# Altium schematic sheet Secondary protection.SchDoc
size 431 x 279 mm; Date: Not shown in title block; ApprovedBy: Not shown in title block; CheckedBy: Not shown in title block; Author: Not shown in title block; CompanyName: Not shown in title block; Engineer: Not shown in title block; Organization: Not shown in title block; Address1: Not shown in title block; Address2: Not shown in title block; Address3: Not shown in title block; Address4: Not shown in title block; DocumentNumber: 1; Revision: Use project parameter SCH_Rev; SheetNumber: 2; SheetTotal: 3; PageSetup: Record=PageOptions¦CenterHorizontal=True¦CenterVertical=True¦PrintScale=1.00¦XCorrection=1.00¦YCorrection=1.00¦PrintKind=0¦BorderSize=5000000¦LeftOffset=0¦BottomOffset=0¦Orientation=2¦PaperLength=1000¦PaperWidth=1000¦Scale=100¦PaperSource=15¦PrintQuality=600¦MediaType=1¦DitherType=10¦PaperKind=Letter¦PrintScaleMode=1
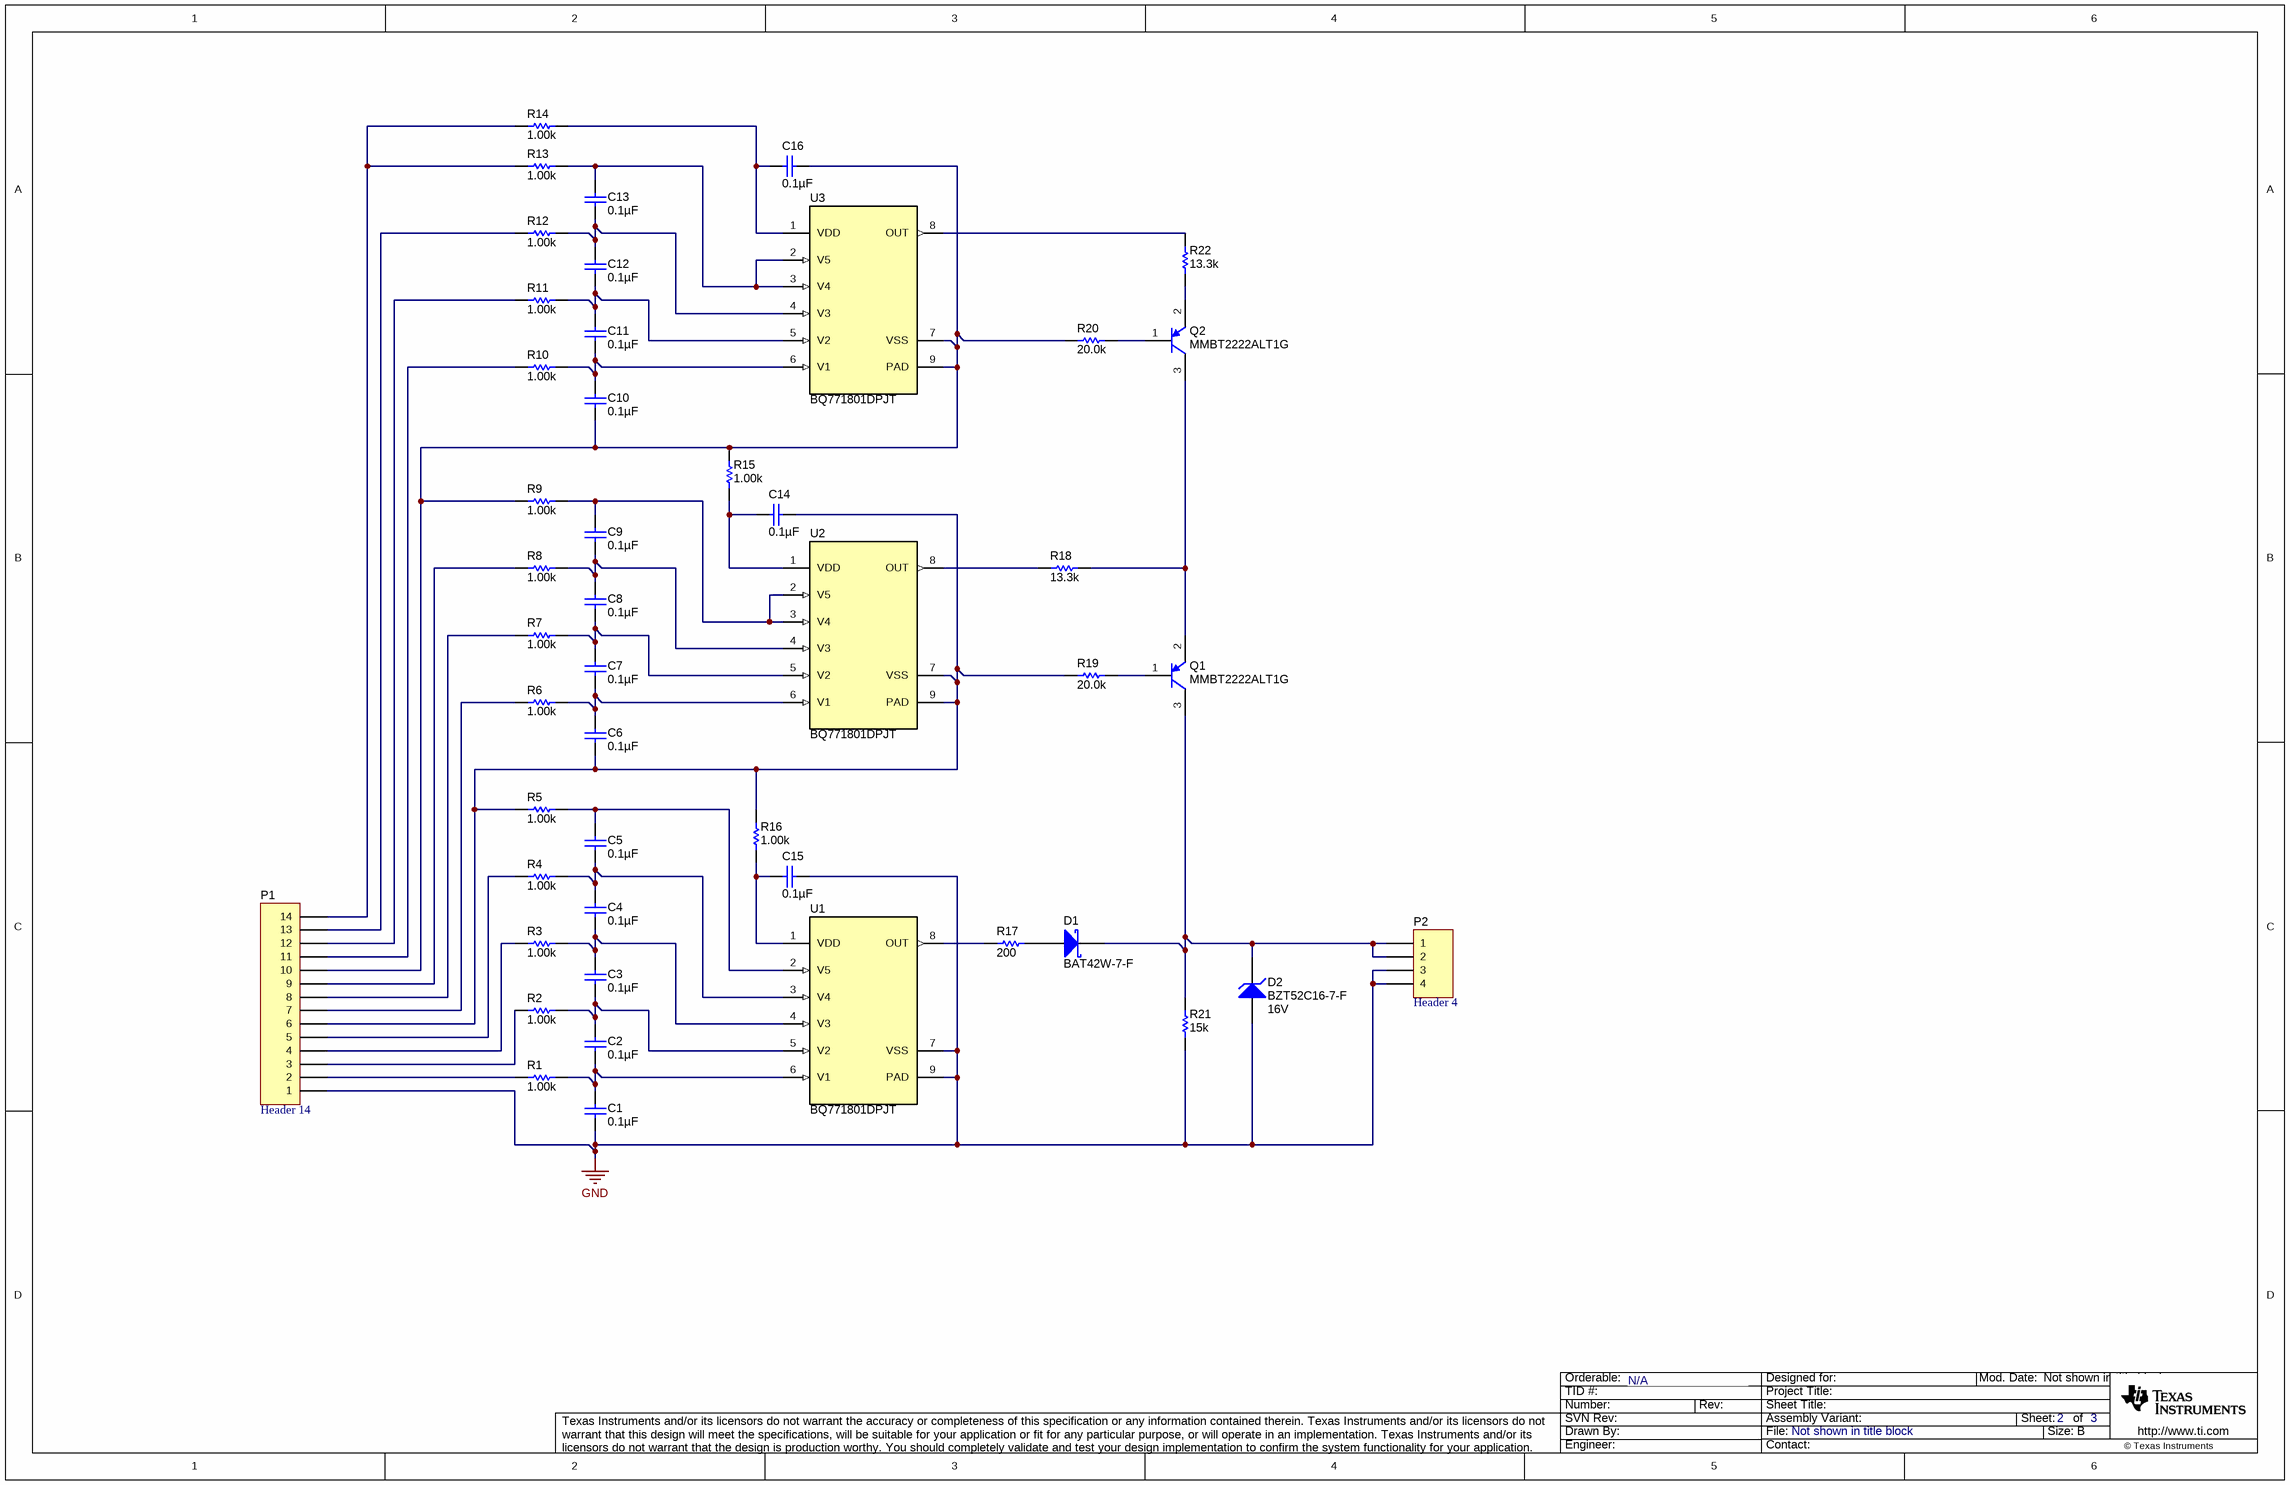
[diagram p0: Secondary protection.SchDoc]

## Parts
C1  ValueDisplayed: 0.1µF  [0603]  (hidden comment: GRM188R71H104KA93D)
C2  ValueDisplayed: 0.1µF  [0603]  (hidden comment: GRM188R71H104KA93D)
C3  ValueDisplayed: 0.1µF  [0603]  (hidden comment: GRM188R71H104KA93D)
C4  ValueDisplayed: 0.1µF  [0603]  (hidden comment: GRM188R71H104KA93D)
C5  ValueDisplayed: 0.1µF  [0603]  (hidden comment: GRM188R71H104KA93D)
C6  ValueDisplayed: 0.1µF  [0603]  (hidden comment: GRM188R71H104KA93D)
C7  ValueDisplayed: 0.1µF  [0603]  (hidden comment: GRM188R71H104KA93D)
C8  ValueDisplayed: 0.1µF  [0603]  (hidden comment: GRM188R71H104KA93D)
C9  ValueDisplayed: 0.1µF  [0603]  (hidden comment: GRM188R71H104KA93D)
C10  ValueDisplayed: 0.1µF  [0603]  (hidden comment: GRM188R71H104KA93D)
C11  ValueDisplayed: 0.1µF  [0603]  (hidden comment: GRM188R71H104KA93D)
C12  ValueDisplayed: 0.1µF  [0603]  (hidden comment: GRM188R71H104KA93D)
C13  ValueDisplayed: 0.1µF  [0603]  (hidden comment: GRM188R71H104KA93D)
C14  ValueDisplayed: 0.1µF  [0603]  (hidden comment: GRM188R71H104KA93D)
C15  ValueDisplayed: 0.1µF  [0603]  (hidden comment: GRM188R71H104KA93D)
C16  ValueDisplayed: 0.1µF  [0603]  (hidden comment: GRM188R71H104KA93D)
D1  BAT42W-7-F  [SOD-123]
D2  BZT52C16-7-F  value 16V  [SOD-123]
P1  Header 14  [HDR1X14]
P2  Header 4  [HDR1X4]
Q1  MMBT2222ALT1G  [SOT-23]
Q2  MMBT2222ALT1G  [SOT-23]
R1  ValueDisplayed: 1.00k  [0603]  (hidden comment: CRCW06031K00FKEA)
R2  ValueDisplayed: 1.00k  [0603]  (hidden comment: CRCW06031K00FKEA)
R3  ValueDisplayed: 1.00k  [0603]  (hidden comment: CRCW06031K00FKEA)
R4  ValueDisplayed: 1.00k  [0603]  (hidden comment: CRCW06031K00FKEA)
R5  ValueDisplayed: 1.00k  [0603]  (hidden comment: CRCW06031K00FKEA)
R6  ValueDisplayed: 1.00k  [0603]  (hidden comment: CRCW06031K00FKEA)
R7  ValueDisplayed: 1.00k  [0603]  (hidden comment: CRCW06031K00FKEA)
R8  ValueDisplayed: 1.00k  [0603]  (hidden comment: CRCW06031K00FKEA)
R9  ValueDisplayed: 1.00k  [0603]  (hidden comment: CRCW06031K00FKEA)
R10  ValueDisplayed: 1.00k  [0603]  (hidden comment: CRCW06031K00FKEA)
R11  ValueDisplayed: 1.00k  [0603]  (hidden comment: CRCW06031K00FKEA)
R12  ValueDisplayed: 1.00k  [0603]  (hidden comment: CRCW06031K00FKEA)
R13  ValueDisplayed: 1.00k  [0603]  (hidden comment: CRCW06031K00FKEA)
R14  ValueDisplayed: 1.00k  [0603]  (hidden comment: CRCW06031K00FKEA)
R15  ValueDisplayed: 1.00k  [0603]  (hidden comment: CRCW06031K00FKEA)
R16  ValueDisplayed: 1.00k  [0603]  (hidden comment: CRCW06031K00FKEA)
R17  ValueDisplayed: 200  [0603]  (hidden comment: CRCW0603200RJNEA)
R18  ValueDisplayed: 13.3k  [0603]  (hidden comment: CRCW060313K3FKEA)
R19  ValueDisplayed: 20.0k  [0603]  (hidden comment: CRCW060320K0FKEA)
R20  ValueDisplayed: 20.0k  [0603]  (hidden comment: CRCW060320K0FKEA)
R21  ValueDisplayed: 15k  [0603]  (hidden comment: CRCW060315K0JNEA)
R22  ValueDisplayed: 13.3k  [0603]  (hidden comment: CRCW060313K3FKEA)
U1  BQ771801DPJT  [DPJ0008A]
U2  BQ771801DPJT  [DPJ0008A]
U3  BQ771801DPJT  [DPJ0008A]

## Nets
GND: C1.2 C15.2 D2.2(A) P1.1 P2.3 P2.4 R21.2 U1.7(VSS) U1.9(PAD)
NetC1_1: C1.1 C2.2 R1.1 U1.6(V1)
NetC2_1: C2.1 C3.2 R2.1 U1.5(V2)
NetC3_1: C3.1 C4.2 R3.1 U1.4(V3)
NetC4_1: C4.1 C5.2 R4.1 U1.3(V4)
NetC5_1: C5.1 R5.1 U1.2(V5)
NetC6_1: C6.1 C7.2 R6.1 U2.6(V1)
NetC6_2: C6.2 C14.2 P1.6 R5.2 R16.1 R19.1 U2.7(VSS) U2.9(PAD)
NetC7_1: C7.1 C8.2 R7.1 U2.5(V2)
NetC8_1: C8.1 C9.2 R8.1 U2.4(V3)
NetC9_1: C9.1 R9.1 U2.2(V5) U2.3(V4)
NetC10_1: C10.1 C11.2 R10.1 U3.6(V1)
NetC10_2: C10.2 C16.2 P1.10 R9.2 R15.1 R20.1 U3.7(VSS) U3.9(PAD)
NetC11_1: C11.1 C12.2 R11.1 U3.5(V2)
NetC12_1: C12.1 C13.2 R12.1 U3.4(V3)
NetC13_1: C13.1 R13.1 U3.2(V5) U3.3(V4)
NetC14_1: C14.1 R15.2 U2.1(VDD)
NetC15_1: C15.1 R16.2 U1.1(VDD)
NetC16_1: C16.1 R14.1 U3.1(VDD)
NetD1_1: D1.1(K) D2.1(K) P2.1 P2.2 Q1.3(C) R21.1
NetD1_2: D1.2(A) R17.2
NetP1_2: P1.2 R1.2
NetP1_3: P1.3 R2.2
NetP1_4: P1.4 R3.2
NetP1_5: P1.5 R4.2
NetP1_7: P1.7 R6.2
NetP1_8: P1.8 R7.2
NetP1_9: P1.9 R8.2
NetP1_11: P1.11 R10.2
NetP1_12: P1.12 R11.2
NetP1_13: P1.13 R12.2
NetP1_14: P1.14 R13.2 R14.2
NetQ1_1: Q1.1(B) R19.2
NetQ1_2: Q1.2(E) Q2.3(C) R18.2
NetQ2_1: Q2.1(B) R20.2
NetQ2_2: Q2.2(E) R22.2
NetR17_1: R17.1 U1.8(OUT)
NetR18_1: R18.1 U2.8(OUT)
NetR22_1: R22.1 U3.8(OUT)

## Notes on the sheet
- N/A

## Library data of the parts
C1-C16 = GRM188R71H104KA93D: CAP, CERM, 0.1 µF, 50 V,+/- 10%, X7R, 0603; Manufacturer: MuRata; Polarized: N; CompType: Capacitor; Value: 0.1uF; U/M: EA; Cap_F: 0.0000001; Tolerance_%: 10; VDC_V: 50; Value2: 50V; TaMin_C: -55; TaMax_C: 125; SizeArea_mm2: 1.28; SizeAreaWB_mm2: 4.68; SizeX_mm: 1.6; SizeY_mm: 0.8; SizeZ_mm: 1; AEC Category: Q200; Green_Lifecycle: Active; Green_REACh: Passed
D1 = BAT42W-7-F: Diode, Schottky, 30 V, 0.2 A, SOD-123; Manufacturer: Diodes Inc.; U/M: EA; Vf_V: 1; Value: 30V; Value1: 0.2A; Value2: 1V; Io_A: 0.2; Vr_V: 30; SizeAreaWB_mm2: 13.095; SizeArea_mm2: 6.545; SizeX_mm: 3.85; SizeY_mm: 1.7; SizeZ_mm: 1.35; AEC Category: Q101; Green_Lifecycle: Not Set; Green_REACh: Incomplete
D2 = BZT52C16-7-F: Diode, Zener, 16 V, 500 mW, AEC-Q101, SOD-123; Manufacturer: Diodes Inc.; SymbolCreator: a0412235; U/M: EA; Power_W: 0.5; Vz_V: 16; Value1: 0.5W; RJA_CperW: 338; SizeAreaWB_mm2: 13.095; SizeArea_mm2: 6.545; SizeX_mm: 3.85; SizeY_mm: 1.7; SizeZ_mm: 1.35; AEC Category: Q101; AEC Qualified: Y
P1 = Header 14: Header, 14-Pin
P2 = Header 4: Header, 4-Pin
Q1 Q2 = MMBT3906-7-F, Diodes Inc.: Transistor, PNP, 40 V, 0.6 A, SOT-23; CompType: BJT; PNP: 1; NPN: 0; Vceo_V: 40; Vcesat1_V: 0.25; Value: 40 V; IcRated_A: 0.2; Value1: 0.2 A; HfeMax: 400; TaMin_C: -55; TaMax_C: 150; SizeAreaWB_mm2: 14; SizeArea_mm2: 7.5; SizeX_mm: 2.5; SizeY_mm: 3; SizeZ_mm: 1.1; U/M: EA; AEC Category: Q101; Green_Lifecycle: Active; Green_REACh: Passed
R1-R16 = CRCW06031K00FKEA: RES, 1.00 k, 1%, 0.1 W, 0603; Manufacturer: Vishay-Dale; CompType: Resistor; Value: 1.00k; Res_ohm: 1000; Value_Code: 1k00; Tolerance_%: 1; Power_W: 0.1; Value2: 0.1W; VDC_V: 75; TempCo: 100 ppm/C; SizeArea_mm2: 1.28; SizeX_mm: 1.6; SizeY_mm: 0.8; EIA_Code: E96; U/M: EA; AEC Category: Q200; Green_Lifecycle: Active; Green_REACh: Passed
R17 = CRCW0603200RJNEA: RES, 200, 5%, 0.1 W, 0603; Manufacturer: Vishay-Dale; CompType: Resistor; Value: 200; Value_Code: 200R; Tolerance_%: 5; Power_W: 0.1; Value2: 0.1W; VDC_V: 75; TempCo: 200 ppm/C; SizeArea_mm2: 1.28; SizeX_mm: 1.6; SizeY_mm: 0.8; SizeZ_mm: 1; EIA_Code: E24; U/M: EA; AEC Category: Q200; Green_Lifecycle: Active; Green_REACh: Passed
R18 R22 = CRCW060313K3FKEA: RES, 13.3 k, 1%, 0.1 W, 0603; Manufacturer: Vishay-Dale; CompType: Resistor; Value: 13.3k; Res_ohm: 13300; Value_Code: 13k3; Tolerance_%: 1; Power_W: 0.1; Value2: 0.1W; VDC_V: 75; TempCo: 100 ppm/C; SizeArea_mm2: 1.28; SizeX_mm: 1.6; SizeY_mm: 0.8; EIA_Code: E96; U/M: EA; AEC Category: Q200; Green_Lifecycle: Active; Green_REACh: Passed
R19 R20 = CRCW060320K0FKEA: RES, 20.0 k, 1%, 0.1 W, 0603; Manufacturer: Vishay-Dale; CompType: Resistor; Value: 20.0k; Res_ohm: 20000; Value_Code: 20k0; Tolerance_%: 1; Power_W: 0.1; Value2: 0.1W; VDC_V: 75; TempCo: 100 ppm/C; SizeArea_mm2: 1.28; SizeX_mm: 1.6; SizeY_mm: 0.8; EIA_Code: E96; U/M: EA; AEC Category: Q200; Green_Lifecycle: Active; Green_REACh: Passed
R21 = CRCW060315K0JNEA: RES, 15 k, 5%, 0.1 W, 0603; Manufacturer: Vishay-Dale; CompType: Resistor; Value: 15k; Res_ohm: 15000; Value_Code: 15k0; Tolerance_%: 5; Power_W: 0.1; Value2: 0.1W; VDC_V: 75; TempCo: 200 ppm/C; SizeArea_mm2: 1.28; SizeX_mm: 1.6; SizeY_mm: 0.8; SizeZ_mm: 1; EIA_Code: E24; U/M: EA; AEC Category: Q200; Green_Lifecycle: Active; Green_REACh: Passed
U1-U3 = CMP-0078897-2: Family 2-5S Overvoltage Protector with Internal Delay Timer, DPJ0008A (WSON-8); Alternate PartNumber: BQ771801DPJR; Alternate Manufacturer: Texas Instruments; SizeAreaWB_mm2: 20; SizeZ_mm: 0.8; SizeX_mm: 4; SizeY_mm: 3; SizeArea_mm2: 12; CompType: IC; AEC Qualified: N; AEC Category: Q200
